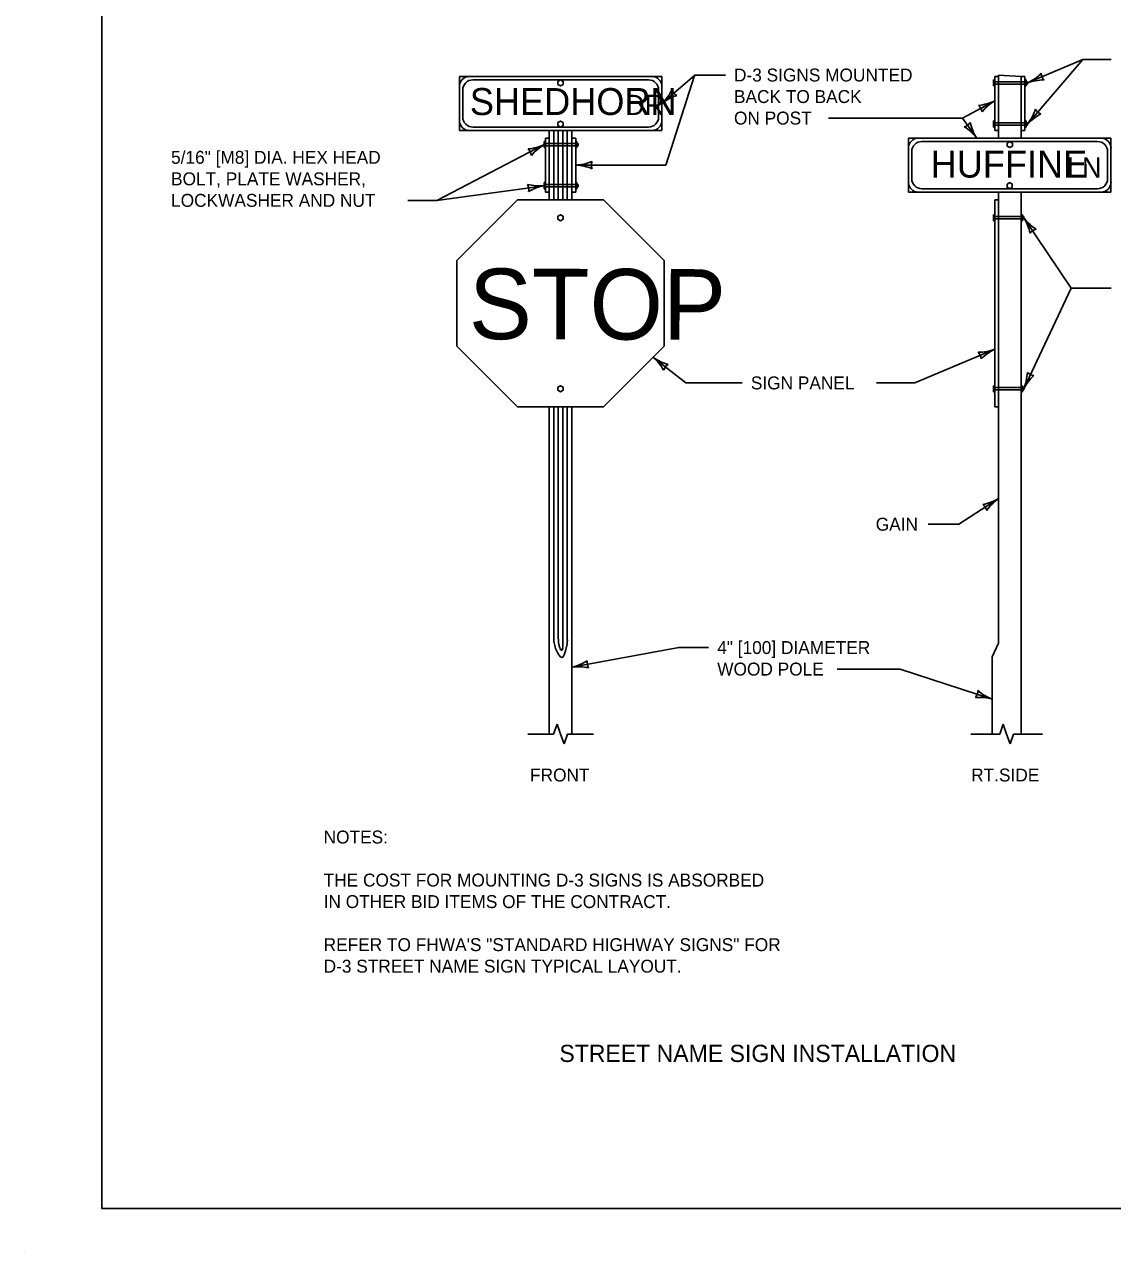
# Model space of a CAD drawing. Extents: x 49991.4 to 50021, y 49987.6 to 50011.4.
# Drawn here: x 49999.02 to 50004.08, y 49987.6 to 49993.3 of the extents above; entities that cross this region are included whole.
import ezdxf

# ---------------------------------------------------------------- set-up
doc = ezdxf.new("R2010")
doc.units = 0
for name, color, linetype in [('Level 1', 7, 'Continuous'), ('Level 2', 7, 'Continuous'), ('Level 3', 7, 'Continuous'), ('Level 4', 7, 'Continuous'), ('Level 6', 7, 'Continuous')]:
    doc.layers.add(name, color=color, linetype=linetype)

msp = doc.modelspace()

# ---------------------------------------------------------------- linework, layer by layer
at = {"layer": 'Level 1'}
for p, q in [((50001.0442, 49993.0577), (50001.0442, 49992.8067)), ((50001.9853, 49993.0577), (50001.0442, 49993.0577)), ((50001.1069, 49993.042), (50001.9226, 49993.042)), ((50001.9853, 49993.0577), (50001.9853, 49992.8067)), ((50003.5252, 49993.0135), (50003.5252, 49993.0417)), ((50003.5252, 49993.0417), (50003.5313, 49993.0417)), ((50003.5252, 49993.0362), (50003.5313, 49993.0362)), ((50003.5313, 49992.8067), (50003.5313, 49993.0577)), ((50003.5313, 49993.0577), (50003.5483, 49993.0577)), ((50003.5483, 49993.064), (50003.6532, 49993.0577)), ((50003.5483, 49993.064), (50003.5483, 49992.7713)), ((50003.671, 49993.0577), (50003.6532, 49993.0577)), ((50003.6532, 49993.0577), (50003.6532, 49992.7713)), ((50003.671, 49992.8067), (50003.671, 49993.0577)), ((50003.671, 49993.0417), (50003.6772, 49993.0417)), ((50003.671, 49993.0362), (50003.6772, 49993.0362)), ((50003.6772, 49993.0135), (50003.6772, 49993.0417)), ((50001.0598, 49992.995), (50001.0598, 49992.8695)), ((50001.9697, 49992.995), (50001.9697, 49992.8695)), ((50003.5252, 49993.0191), (50003.5313, 49993.0191)), ((50003.5252, 49993.0135), (50003.5313, 49993.0135)), ((50003.671, 49993.0191), (50003.6772, 49993.0191)), ((50003.671, 49993.0135), (50003.6772, 49993.0135)), ((50003.6772, 49993.0333), (50003.6833, 49993.0333)), ((50003.6772, 49993.022), (50003.6833, 49993.022)), ((50003.6833, 49993.022), (50003.6833, 49993.0333)), ((50001.0442, 49992.8067), (50001.9853, 49992.8067)), ((50001.1069, 49992.8225), (50001.9226, 49992.8225)), ((50001.4619, 49992.8067), (50001.4619, 49992.4849)), ((50001.4829, 49992.8067), (50001.4829, 49992.4849)), ((50001.5038, 49992.8067), (50001.5038, 49992.4849)), ((50001.5248, 49992.8067), (50001.5248, 49992.4849)), ((50001.5457, 49992.8067), (50001.5457, 49992.4849)), ((50001.5666, 49992.8067), (50001.5666, 49992.4849)), ((50003.5252, 49992.8227), (50003.5252, 49992.8509)), ((50003.5252, 49992.8509), (50003.5313, 49992.8509)), ((50003.5252, 49992.8453), (50003.5313, 49992.8453)), ((50003.5252, 49992.8282), (50003.5313, 49992.8282)), ((50003.5252, 49992.8227), (50003.5313, 49992.8227)), ((50003.5483, 49992.8067), (50003.5313, 49992.8067)), ((50003.654, 49992.8067), (50003.671, 49992.8067)), ((50003.671, 49992.8509), (50003.6772, 49992.8509)), ((50003.671, 49992.8453), (50003.6772, 49992.8453)), ((50003.671, 49992.8282), (50003.6772, 49992.8282)), ((50003.671, 49992.8227), (50003.6772, 49992.8227)), ((50003.6772, 49992.8227), (50003.6772, 49992.8509)), ((50003.6772, 49992.8424), (50003.6833, 49992.8424)), ((50003.6772, 49992.8311), (50003.6833, 49992.8311)), ((50003.6833, 49992.8311), (50003.6833, 49992.8424)), ((50001.4388, 49992.7272), (50001.4388, 49992.7553)), ((50001.4388, 49992.7553), (50001.4449, 49992.7553)), ((50001.4388, 49992.7498), (50001.4449, 49992.7498)), ((50001.4449, 49992.7714), (50001.4619, 49992.7714)), ((50001.4449, 49992.5204), (50001.4449, 49992.7713)), ((50001.5845, 49992.7714), (50001.5675, 49992.7714)), ((50001.5845, 49992.5204), (50001.5845, 49992.7713)), ((50001.5845, 49992.7553), (50001.5906, 49992.7553)), ((50001.5845, 49992.7498), (50001.5906, 49992.7498)), ((50001.5906, 49992.7272), (50001.5906, 49992.7553)), ((50003.13, 49992.7713), (50003.13, 49992.5204)), ((50004.071, 49992.7713), (50003.13, 49992.7713)), ((50003.1927, 49992.7557), (50004.0083, 49992.7557)), ((50004.071, 49992.7713), (50004.071, 49992.5204)), ((50001.4388, 49992.7327), (50001.4449, 49992.7327)), ((50001.4388, 49992.7272), (50001.4449, 49992.7272)), ((50001.5845, 49992.7327), (50001.5906, 49992.7327)), ((50001.5845, 49992.7272), (50001.5906, 49992.7272)), ((50001.5906, 49992.7469), (50001.5968, 49992.7469)), ((50001.5906, 49992.7356), (50001.5968, 49992.7356)), ((50001.5968, 49992.7356), (50001.5968, 49992.7469)), ((50003.1457, 49992.7086), (50003.1457, 49992.5831)), ((50004.0554, 49992.7086), (50004.0554, 49992.5831)), ((50001.4388, 49992.5364), (50001.4388, 49992.5645)), ((50001.4388, 49992.5645), (50001.4449, 49992.5645)), ((50001.4388, 49992.559), (50001.4449, 49992.559)), ((50001.4388, 49992.5419), (50001.4449, 49992.5419)), ((50001.4388, 49992.5364), (50001.4449, 49992.5364)), ((50001.5845, 49992.5645), (50001.5906, 49992.5645)), ((50001.5845, 49992.559), (50001.5906, 49992.559)), ((50001.5845, 49992.5419), (50001.5906, 49992.5419)), ((50001.5845, 49992.5364), (50001.5906, 49992.5364)), ((50001.5906, 49992.5364), (50001.5906, 49992.5645)), ((50001.5906, 49992.5561), (50001.5968, 49992.5561)), ((50001.5906, 49992.5448), (50001.5968, 49992.5448)), ((50001.5968, 49992.5448), (50001.5968, 49992.5561)), ((50003.1927, 49992.536), (50004.0083, 49992.536)), ((50001.4619, 49992.5204), (50001.4449, 49992.5204)), ((50001.5845, 49992.5204), (50001.5675, 49992.5204)), ((50003.13, 49992.5204), (50004.071, 49992.5204)), ((50003.5314, 49992.4849), (50003.5314, 49991.5231)), ((50003.5483, 49992.4849), (50003.5314, 49992.4849)), ((50003.5483, 49992.5204), (50003.5483, 49990.4248)), ((50003.6532, 49992.5204), (50003.6532, 49990.0028)), ((50003.5253, 49992.3872), (50003.5253, 49992.4153)), ((50003.5253, 49992.4153), (50003.5314, 49992.4153)), ((50003.5253, 49992.4098), (50003.5314, 49992.4098)), ((50003.6532, 49992.4153), (50003.6593, 49992.4153)), ((50003.6532, 49992.4098), (50003.6593, 49992.4098)), ((50003.6593, 49992.3872), (50003.6593, 49992.4153)), ((50003.5253, 49992.3927), (50003.5314, 49992.3927)), ((50003.5253, 49992.3872), (50003.5314, 49992.3872)), ((50003.6532, 49992.3927), (50003.6593, 49992.3927)), ((50003.6532, 49992.3872), (50003.6593, 49992.3872)), ((50003.6593, 49992.4069), (50003.6654, 49992.4069)), ((50003.6593, 49992.3956), (50003.6654, 49992.3956)), ((50003.6654, 49992.3956), (50003.6654, 49992.4069)), ((50003.5253, 49991.5928), (50003.5253, 49991.6209)), ((50003.5253, 49991.6209), (50003.5314, 49991.6209)), ((50003.5253, 49991.6154), (50003.5314, 49991.6154)), ((50003.6532, 49991.6209), (50003.6593, 49991.6209)), ((50003.6532, 49991.6154), (50003.6593, 49991.6154)), ((50003.6593, 49991.5928), (50003.6593, 49991.6209)), ((50003.6593, 49991.6125), (50003.6654, 49991.6125)), ((50003.6654, 49991.6012), (50003.6654, 49991.6125)), ((50003.5253, 49991.5983), (50003.5314, 49991.5983)), ((50003.5253, 49991.5928), (50003.5314, 49991.5928)), ((50003.6532, 49991.5983), (50003.6593, 49991.5983)), ((50003.6532, 49991.5928), (50003.6593, 49991.5928)), ((50003.6593, 49991.6012), (50003.6654, 49991.6012)), ((50001.4619, 49991.5231), (50001.4619, 49990.0028)), ((50001.4829, 49991.5231), (50001.4829, 49990.4471)), ((50001.5038, 49991.5231), (50001.5038, 49990.4467)), ((50001.5248, 49991.5231), (50001.5248, 49990.4465)), ((50001.5457, 49991.5231), (50001.5457, 49990.4472)), ((50001.5666, 49991.5231), (50001.5666, 49990.0028)), ((50003.5314, 49991.5231), (50003.5483, 49991.5231)), ((50003.5195, 49990.361), (50003.5483, 49990.4248)), ((50003.5195, 49990.361), (50003.5195, 49990.0028)), ((49999.0245, 49987.5988), (49999.0245, 49987.5988))]:
    msp.add_line(p, q, dxfattribs=at)
for points in [[(49999.3835, 49998.9992), (50016.7501, 49998.9992), (50016.7501, 49987.7988), (49999.3835, 49987.7988)], [(50001.5023, 49993.0345), (50001.5023, 49993.0205), (50001.5145, 49993.0135), (50001.5266, 49993.0205), (50001.5266, 49993.0345), (50001.5145, 49993.0416)], [(50001.5022, 49992.8436), (50001.5022, 49992.8296), (50001.5144, 49992.8226), (50001.5266, 49992.8296), (50001.5266, 49992.8436), (50001.5144, 49992.8507)], [(50003.5886, 49992.7483), (50003.5886, 49992.7342), (50003.6007, 49992.7272), (50003.6129, 49992.7342), (50003.6129, 49992.7483), (50003.6007, 49992.7553)], [(50003.5884, 49992.5574), (50003.5884, 49992.5434), (50003.6006, 49992.5364), (50003.6127, 49992.5434), (50003.6127, 49992.5574), (50003.6006, 49992.5645)], [(50001.9948, 49991.8048), (50001.9948, 49992.2032), (50001.7131, 49992.4849), (50001.3147, 49992.4849), (50001.033, 49992.2032), (50001.033, 49991.8048), (50001.3147, 49991.5231), (50001.7131, 49991.5231)], [(50001.5021, 49992.4083), (50001.5021, 49992.3942), (50001.5142, 49992.3872), (50001.5264, 49992.3942), (50001.5264, 49992.4083), (50001.5142, 49992.4153)], [(50001.5017, 49991.6138), (50001.5017, 49991.5998), (50001.5139, 49991.5928), (50001.526, 49991.5998), (50001.526, 49991.6138), (50001.5139, 49991.6209)]]:
    msp.add_lwpolyline(points, close=True, dxfattribs=at)
for points in [[(50001.5248, 49990.4465), (50001.5251, 49990.4435), (50001.5254, 49990.4412), (50001.5251, 49990.4384), (50001.5249, 49990.4353), (50001.5242, 49990.4311), (50001.5242, 49990.4283), (50001.5247, 49990.4248), (50001.5251, 49990.4225), (50001.5254, 49990.4202), (50001.5258, 49990.4181), (50001.5256, 49990.4151), (50001.5256, 49990.4125), (50001.5254, 49990.4102), (50001.5254, 49990.4076), (50001.5251, 49990.405)], [(50001.5457, 49990.4479), (50001.5455, 49990.4454), (50001.5457, 49990.4423), (50001.546, 49990.4395), (50001.546, 49990.437), (50001.5457, 49990.4344), (50001.5455, 49990.4316), (50001.5455, 49990.429), (50001.5457, 49990.426), (50001.5453, 49990.4237), (50001.5446, 49990.4214), (50001.5443, 49990.419), (50001.5441, 49990.4165), (50001.5434, 49990.4141), (50001.5429, 49990.4118), (50001.5422, 49990.409), (50001.5415, 49990.4067), (50001.541, 49990.4046), (50001.541, 49990.4022)]]:
    msp.add_lwpolyline(points, dxfattribs=at)
for centre, radius, start, end in [((50001.0912, 49993.0107), 0.047, 89.9588, 179.9588), ((50001.1068, 49992.995), 0.0471, 89.9391, 179.9391), ((50001.9226, 49992.9949), 0.0471, 0.1121, 90.1121), ((50001.9382, 49993.0106), 0.0471, 0.0882, 90.0882), ((50001.1076, 49992.8703), 0.0478, 180.9618, 270.9618), ((50001.9226, 49992.8696), 0.0471, 269.9236, 359.9236), ((50001.0913, 49992.8538), 0.0471, 179.9842, 269.9842), ((50001.9381, 49992.8539), 0.0472, 269.9248, 359.9248), ((50003.1771, 49992.7243), 0.0471, 90, 180), ((50003.1928, 49992.7086), 0.0471, 90, 180), ((50004.0084, 49992.7086), 0.0471, 0, 90), ((50004.0241, 49992.7243), 0.0471, 0, 90), ((50003.1928, 49992.5831), 0.0471, 180, 270), ((50004.0084, 49992.5831), 0.0471, 270, 0), ((50003.1771, 49992.5674), 0.0471, 180, 270), ((50004.0241, 49992.5674), 0.0471, 270, 0)]:
    msp.add_arc(centre, radius, start, end, dxfattribs=at)
for points in [[(50001.4828, 49990.4503), (50001.4856, 49990.4197), (50001.494, 49990.3935), (50001.5202, 49990.3585), (50001.5409, 49990.4)], [(50001.5038, 49990.4482), (50001.5062, 49990.42), (50001.513, 49990.3988), (50001.5188, 49990.3911), (50001.5246, 49990.4026)]]:
    msp.add_spline(points, degree=3, dxfattribs=at)
at = {"layer": 'Level 3'}
for p, q in [((50003.6833, 49993.0276), (50003.9402, 49993.1361)), ((50003.6833, 49992.8368), (50003.9402, 49993.1361)), ((50004.0721, 49993.1361), (50003.9402, 49993.1361)), ((50001.9853, 49992.9322), (50002.1383, 49993.0644)), ((50002.1363, 49993.0626), (50002.0032, 49992.6458)), ((50002.2798, 49993.0644), (50002.1383, 49993.0644)), ((50003.3816, 49992.8644), (50003.5313, 49992.9447)), ((50002.759, 49992.8644), (50003.3816, 49992.8644)), ((50003.3816, 49992.8644), (50003.4472, 49992.7713)), ((50001.4388, 49992.7412), (50000.9394, 49992.4821)), ((50001.5845, 49992.6458), (50002.0032, 49992.6458)), ((50001.4388, 49992.5504), (50000.9394, 49992.4821)), ((50000.8043, 49992.4821), (50000.9394, 49992.4821)), ((50003.6654, 49992.4012), (50003.8859, 49992.0741)), ((50003.6654, 49991.6068), (50003.8859, 49992.0741)), ((50004.0721, 49992.0741), (50003.8859, 49992.0741)), ((50003.1597, 49991.634), (50003.5314, 49991.7903)), ((50002.0955, 49991.634), (50001.9436, 49991.7535)), ((50002.3581, 49991.634), (50002.0955, 49991.634)), ((50002.9821, 49991.634), (50003.1597, 49991.634)), ((50003.3648, 49990.9775), (50003.5483, 49991.0963)), ((50003.2213, 49990.9775), (50003.3648, 49990.9775)), ((50002.0642, 49990.4045), (50001.5666, 49990.3131)), ((50002.202, 49990.4045), (50002.0642, 49990.4045)), ((50002.7988, 49990.3045), (50003.0911, 49990.3045)), ((50003.0911, 49990.3045), (50003.5198, 49990.1649))]:
    msp.add_line(p, q, dxfattribs=at)
for centre, radius, start, end in [((50003.5822, 49993.2375), 0.233, 295.7251, 314.975), ((50003.7613, 49992.8194), 0.2223, 90.3538, 110.5373), ((50003.8014, 49993.0775), 0.0548, 185.0366, 220.759), ((50001.8244, 49993.1011), 0.233, 313.656, 332.9059), ((50002.0823, 49993.0164), 0.0548, 202.9675, 238.6899), ((50002.1236, 49992.7585), 0.2223, 108.2847, 128.4683), ((50003.4344, 49993.1448), 0.2223, 275.6654, 295.8489), ((50003.4183, 49992.8841), 0.0548, 10.3482, 46.0706), ((50003.6514, 49992.7451), 0.233, 121.0367, 140.2865), ((50003.4992, 49992.9797), 0.233, 322.182, 341.4319), ((50003.8459, 49992.6852), 0.2223, 116.8107, 136.9942), ((50003.7668, 49992.9341), 0.0548, 211.4935, 247.2159), ((50003.3733, 49992.8761), 0.0548, 287.3081, 323.0304), ((50003.2636, 49992.6279), 0.233, 37.9965, 57.2464), ((50003.6341, 49992.8918), 0.2223, 192.6253, 212.8088), ((50001.3446, 49992.9426), 0.2223, 274.8773, 295.0608), ((50001.325, 49992.6822), 0.0548, 9.5601, 45.2825), ((50001.5562, 49992.5399), 0.233, 120.2486, 139.4985), ((50001.573, 49992.8785), 0.233, 272.8273, 292.0772), ((50001.5753, 49992.4237), 0.2223, 67.456, 87.6395), ((50001.7127, 49992.6458), 0.0548, 162.1388, 197.8612), ((50001.416, 49992.7715), 0.2223, 255.7096, 275.8931), ((50001.3119, 49992.532), 0.0548, 350.3924, 26.1148), ((50001.4836, 49992.3217), 0.233, 101.0809, 120.3308), ((50003.4781, 49992.2815), 0.2223, 12.3948, 32.5783), ((50003.8496, 49992.5439), 0.233, 217.7661, 237.016), ((50003.7388, 49992.2961), 0.0548, 107.0776, 142.8), ((50003.4537, 49991.9986), 0.2223, 270.2628, 290.4463), ((50003.6322, 49991.5802), 0.233, 115.6341, 134.8839), ((50001.7991, 49991.5846), 0.2223, 29.2638, 49.4473), ((50002.0785, 49991.9435), 0.233, 234.6351, 253.885), ((50003.4132, 49991.7406), 0.0548, 4.9456, 40.668), ((50002.0444, 49991.6742), 0.0548, 123.9466, 159.669), ((50003.45, 49991.6957), 0.233, 337.5666, 356.8164), ((50003.8624, 49991.5037), 0.2223, 132.1953, 152.3788), ((50003.7201, 49991.7228), 0.0548, 226.8781, 262.6004), ((50003.4353, 49991.2877), 0.2223, 280.3755, 300.559), ((50003.6844, 49990.9072), 0.233, 125.7468, 144.9966), ((50003.4407, 49991.0266), 0.0548, 15.0583, 50.7807), ((50001.5133, 49990.5399), 0.233, 283.2355, 302.4853), ((50001.5977, 49990.093), 0.2223, 77.8642, 98.0477), ((50001.6927, 49990.3363), 0.0548, 172.547, 208.2694), ((50003.3979, 49990.2046), 0.0548, 324.1017, 359.8241), ((50003.5973, 49990.3733), 0.2223, 229.4189, 249.6024), ((50003.4587, 49989.9401), 0.233, 74.7902, 94.0401)]:
    msp.add_arc(centre, radius, start, end, dxfattribs=at)
at = {"layer": 'Level 4'}
for p, q in [((50003.5313, 49993.0333), (50003.671, 49993.0333)), ((50003.5313, 49993.022), (50003.671, 49993.022)), ((50003.5313, 49992.8424), (50003.671, 49992.8424)), ((50003.5313, 49992.8311), (50003.671, 49992.8311)), ((50001.4449, 49992.7469), (50001.5845, 49992.7469)), ((50001.4449, 49992.7356), (50001.5845, 49992.7356)), ((50001.4449, 49992.5561), (50001.5845, 49992.5561)), ((50001.4449, 49992.5448), (50001.5845, 49992.5448)), ((50003.5314, 49992.4069), (50003.6593, 49992.4069)), ((50003.5314, 49992.3956), (50003.6593, 49992.3956)), ((50003.5314, 49991.6125), (50003.6593, 49991.6125)), ((50003.5314, 49991.6012), (50003.6593, 49991.6012))]:
    msp.add_line(p, q, dxfattribs=at)
at = {"layer": 'Level 6'}
for p, q in [((50001.4981, 49990.0485), (50001.4819, 49990.0028)), ((50001.4981, 49990.0485), (50001.5143, 49990.0028)), ((50003.5701, 49990.0485), (50003.5539, 49990.0028)), ((50003.5701, 49990.0485), (50003.5863, 49990.0028)), ((50001.4819, 49990.0028), (50001.3619, 49990.0028)), ((50001.5143, 49990.0028), (50001.5305, 49989.9571)), ((50001.5467, 49990.0028), (50001.5305, 49989.9571)), ((50001.6666, 49990.0028), (50001.5467, 49990.0028)), ((50003.5539, 49990.0028), (50003.4195, 49990.0028)), ((50003.5863, 49990.0028), (50003.6025, 49989.9571)), ((50003.6187, 49990.0028), (50003.6025, 49989.9571)), ((50003.7532, 49990.0028), (50003.6187, 49990.0028))]:
    msp.add_line(p, q, dxfattribs=at)

# ---------------------------------------------------------------- texts
at = {"layer": 'Level 1'}
for s, height, rotation, p in [('SHEDHORN', 0.12546, 0.0001, (50001.0931, 49992.8784)), ('DR', 0.09409, 359.999, (50001.8142, 49992.8784)), ('HUFFINE', 0.12546, 0.0001, (50003.2335, 49992.5879)), ('LN', 0.09409, 359.999, (50003.8665, 49992.5879)), ('STOP', 0.32792, 359.8333, (50001.0882, 49991.8376))]:
    msp.add_text(s, height=height, rotation=rotation, dxfattribs=at).set_placement(p)
at = {"layer": 'Level 2'}
for s, height, p in [('D-3 SIGNS MOUNTED', 0.06, (50002.3198, 49993.0344)), ('BACK TO BACK', 0.06, (50002.3198, 49992.9344)), ('ON POST', 0.06, (50002.3198, 49992.8344)), ('5/16" [M8] DIA. HEX HEAD', 0.06, (49999.7051, 49992.6521)), ('BOLT, PLATE WASHER,', 0.06, (49999.7051, 49992.5521)), ('LOCKWASHER AND NUT', 0.06, (49999.7051, 49992.4521)), ('SIGN PANEL', 0.06, (50002.3981, 49991.604)), ('GAIN', 0.06, (50002.9783, 49990.9475)), ('4" [100] DIAMETER', 0.06, (50002.242, 49990.3745)), ('WOOD POLE', 0.06, (50002.242, 49990.2745)), ('FRONT', 0.06, (50001.3726, 49989.7823)), ('RT.SIDE', 0.06, (50003.4214, 49989.7823)), ('NOTES:', 0.06, (50000.4138, 49989.4942)), ('THE COST FOR MOUNTING D-3 SIGNS IS ABSORBED', 0.06, (50000.4138, 49989.2942)), ('IN OTHER BID ITEMS OF THE CONTRACT.', 0.06, (50000.4138, 49989.1942)), ('REFER TO FHWA\'S "STANDARD HIGHWAY SIGNS" FOR', 0.06, (50000.4138, 49988.9942)), ('D-3 STREET NAME SIGN TYPICAL LAYOUT.', 0.06, (50000.4138, 49988.8942)), ('STREET NAME SIGN INSTALLATION', 0.08, (50001.5088, 49988.4791))]:
    msp.add_text(s, height=height, dxfattribs=at).set_placement(p)

doc.saveas('drawing.dxf')
